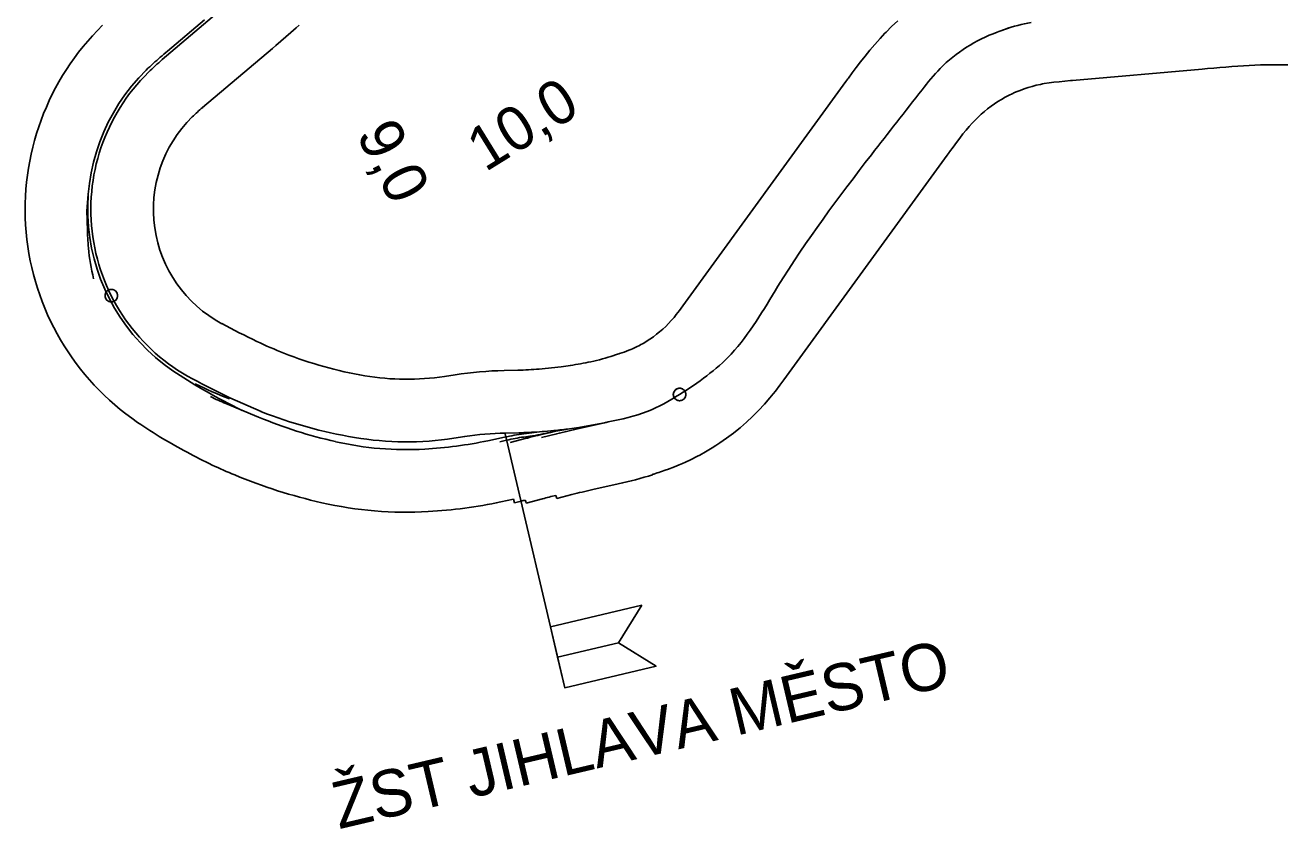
# Model space of a CAD drawing. Extents: x -670810 to -649614, y -1131928 to -1115069.
# Drawn here: x -670304 to -668294, y -1129775 to -1128491 of the extents above; entities that cross this region are included whole.
import ezdxf

# ---------------------------------------------------------------- set-up
doc = ezdxf.new("R2010")
doc.units = 0
for name, color, linetype in [('519 Var SK-4 Praporky stanic', 7, 'Continuous'), ('hranice_VRT_ZUR_Vysocina', 7, 'Continuous'), ('Osa koleje', 7, 'Continuous'), ('Osa koleje úprava GPK', 7, 'Continuous'), ('Situace - Osa koleje 2D', 7, 'Continuous'), ('Staničení - hlavní staničení + kolečka 1k', 7, 'Continuous')]:
    doc.layers.add(name, color=color, linetype=linetype)

# ---------------------------------------------------------------- blocks, each defined once
blk = doc.blocks.new('Sit10Kruh_176')
at = {"layer": 'Staničení - hlavní staničení + kolečka 1k'}
blk.add_lwpolyline([(10, 0), (10, 0.6), (9.9, 1.3), (9.8, 1.9), (9.7, 2.5), (9.5, 3.1), (9.3, 3.7), (9, 4.3), (8.8, 4.8), (8.4, 5.4), (8.1, 5.9), (7.7, 6.4), (7.3, 6.8), (6.8, 7.3), (6.4, 7.7), (5.9, 8.1), (5.4, 8.4), (4.8, 8.8), (4.3, 9), (3.7, 9.3), (3.1, 9.5), (2.5, 9.7), (1.9, 9.8), (1.3, 9.9), (0.6, 10), (0, 10), (-0.6, 10), (-1.3, 9.9), (-1.9, 9.8), (-2.5, 9.7), (-3.1, 9.5), (-3.7, 9.3), (-4.3, 9), (-4.8, 8.8), (-5.4, 8.4), (-5.9, 8.1), (-6.4, 7.7), (-6.8, 7.3), (-7.3, 6.8), (-7.7, 6.4), (-8.1, 5.9), (-8.4, 5.4), (-8.8, 4.8), (-9, 4.3), (-9.3, 3.7), (-9.5, 3.1), (-9.7, 2.5), (-9.8, 1.9), (-9.9, 1.3), (-10, 0.6), (-10, 0), (-10, -0.6), (-9.9, -1.3), (-9.8, -1.9), (-9.7, -2.5), (-9.5, -3.1), (-9.3, -3.7), (-9, -4.3), (-8.8, -4.8), (-8.4, -5.4), (-8.1, -5.9), (-7.7, -6.4), (-7.3, -6.8), (-6.8, -7.3), (-6.4, -7.7), (-5.9, -8.1), (-5.4, -8.4), (-4.8, -8.8), (-4.3, -9), (-3.7, -9.3), (-3.1, -9.5), (-2.5, -9.7), (-1.9, -9.8), (-1.3, -9.9), (-0.6, -10), (0, -10), (0.6, -10), (1.3, -9.9), (1.9, -9.8), (2.5, -9.7), (3.1, -9.5), (3.7, -9.3), (4.3, -9), (4.8, -8.8), (5.4, -8.4), (5.9, -8.1), (6.4, -7.7), (6.8, -7.3), (7.3, -6.8), (7.7, -6.4), (8.1, -5.9), (8.4, -5.4), (8.8, -4.8), (9, -4.3), (9.3, -3.7), (9.5, -3.1), (9.7, -2.5), (9.8, -1.9), (9.9, -1.3)], close=True, dxfattribs=at)
blk.add_circle((0, 0), 10, dxfattribs=at)
blk = doc.blocks.new('Sit10Kruh_230')
at = {"layer": 'Staničení - hlavní staničení + kolečka 1k'}
blk.add_lwpolyline([(10, 0), (10, 0.6), (9.9, 1.3), (9.8, 1.9), (9.7, 2.5), (9.5, 3.1), (9.3, 3.7), (9, 4.3), (8.8, 4.8), (8.4, 5.4), (8.1, 5.9), (7.7, 6.4), (7.3, 6.8), (6.8, 7.3), (6.4, 7.7), (5.9, 8.1), (5.4, 8.4), (4.8, 8.8), (4.3, 9), (3.7, 9.3), (3.1, 9.5), (2.5, 9.7), (1.9, 9.8), (1.3, 9.9), (0.6, 10), (0, 10), (-0.6, 10), (-1.3, 9.9), (-1.9, 9.8), (-2.5, 9.7), (-3.1, 9.5), (-3.7, 9.3), (-4.3, 9), (-4.8, 8.8), (-5.4, 8.4), (-5.9, 8.1), (-6.4, 7.7), (-6.8, 7.3), (-7.3, 6.8), (-7.7, 6.4), (-8.1, 5.9), (-8.4, 5.4), (-8.8, 4.8), (-9, 4.3), (-9.3, 3.7), (-9.5, 3.1), (-9.7, 2.5), (-9.8, 1.9), (-9.9, 1.3), (-10, 0.6), (-10, 0), (-10, -0.6), (-9.9, -1.3), (-9.8, -1.9), (-9.7, -2.5), (-9.5, -3.1), (-9.3, -3.7), (-9, -4.3), (-8.8, -4.8), (-8.4, -5.4), (-8.1, -5.9), (-7.7, -6.4), (-7.3, -6.8), (-6.8, -7.3), (-6.4, -7.7), (-5.9, -8.1), (-5.4, -8.4), (-4.8, -8.8), (-4.3, -9), (-3.7, -9.3), (-3.1, -9.5), (-2.5, -9.7), (-1.9, -9.8), (-1.3, -9.9), (-0.6, -10), (0, -10), (0.6, -10), (1.3, -9.9), (1.9, -9.8), (2.5, -9.7), (3.1, -9.5), (3.7, -9.3), (4.3, -9), (4.8, -8.8), (5.4, -8.4), (5.9, -8.1), (6.4, -7.7), (6.8, -7.3), (7.3, -6.8), (7.7, -6.4), (8.1, -5.9), (8.4, -5.4), (8.8, -4.8), (9, -4.3), (9.3, -3.7), (9.5, -3.1), (9.7, -2.5), (9.8, -1.9), (9.9, -1.3)], close=True, dxfattribs=at)
blk.add_circle((0, 0), 10, dxfattribs=at)
blk = doc.blocks.new('_U648')
at = {"layer": 'Staničení - hlavní staničení + kolečka 1k', "rotation": -63.32941}
blk.add_blockref('Sit10Kruh_230', (-261.6, -148.2), dxfattribs=at)
at = {"layer": 'Staničení - hlavní staničení + kolečka 1k'}
blk.add_text('9,0', height=70, rotation=296.6706, dxfattribs=at).set_placement((129.2, 109.6))

msp = doc.modelspace()

# ---------------------------------------------------------------- linework, layer by layer
at = {"layer": '519 Var SK-4 Praporky stanic'}
for p, q in [((-669537, -1129143.7), (-669441.6, -1129549.6)), ((-669464.5, -1129452.3), (-669318.4, -1129417.9)), ((-669453, -1129500.9), (-669355.7, -1129478))]:
    msp.add_line(p, q, dxfattribs=at)
for points in [[(-669318.4, -1129417.9), (-669355.7, -1129478), (-669453, -1129500.9), (-669464.5, -1129452.3)], [(-669453, -1129500.9), (-669355.7, -1129478), (-669355.7, -1129478), (-669295.5, -1129515.3), (-669441.6, -1129549.6)]]:
    msp.add_lwpolyline(points, close=True, dxfattribs=at)
at = {"layer": 'hranice_VRT_ZUR_Vysocina'}
for p, q in [((-669516.7, -1129042.2), (-669538.5, -1129042.7)), ((-669482.7, -1129040.4), (-669467.7, -1129039)), ((-669447.5, -1129036.7), (-669432.6, -1129034.7)), ((-669633.9, -1129052.1), (-669616.6, -1129049.4)), ((-669396.7, -1129233), (-669356.1, -1129223.9)), ((-669477.3, -1129247.7), (-669503.2, -1129254.5)), ((-669454.4, -1129247), (-669455.6, -1129242.2)), ((-669430.2, -1129240.9), (-669454.4, -1129247)), ((-669543.8, -1129252.8), (-669523.4, -1129248.5)), ((-669522.1, -1129254.1), (-669523.4, -1129248.5)), ((-669522.1, -1129254.1), (-669511.2, -1129251.5)), ((-669503.2, -1129254.5), (-669504.3, -1129250))]:
    msp.add_line(p, q, dxfattribs=at)
for points in [[(-669866.1, -1128490.7), (-669870.9, -1128495.1), (-669879.2, -1128502.5), (-669887.4, -1128509.7), (-669895.5, -1128516.6), (-669903.3, -1128523.3), (-669908.9, -1128528), (-670020.3, -1128622.4)], [(-669363.2, -1129018.8), (-669361.8, -1129018.4), (-669357.2, -1129016.8), (-669355.3, -1129016.2), (-669354.1, -1129015.8), (-669346.7, -1129013.2), (-669339.2, -1129010.3), (-669335.8, -1129009), (-669333.3, -1129007.9), (-669331.2, -1129006.9), (-669327.8, -1129005.4), (-669321.1, -1129002), (-669320.9, -1129001.9), (-669316.3, -1128999.4), (-669310.2, -1128995.7), (-669308.2, -1128994.5), (-669305.5, -1128992.7), (-669299.9, -1128988.8), (-669294.7, -1128984.9), (-669290.1, -1128981.2), (-669284.9, -1128976.7), (-669280.2, -1128972.3), (-669275.7, -1128967.8), (-669271.3, -1128963.1), (-669266.9, -1128958), (-669264.5, -1128955), (-669263.2, -1128953.4), (-669258.2, -1128946.8), (-669252.8, -1128939.5), (-668992.1, -1128581.2), (-668988.8, -1128576.6), (-668988.1, -1128575.6), (-668981.9, -1128567.2), (-668975.5, -1128558.5), (-668968.7, -1128549.5), (-668961.6, -1128540.4), (-668954, -1128531.1), (-668946, -1128521.6), (-668937.6, -1128512.1), (-668929.7, -1128503.8), (-668928, -1128502), (-668919.1, -1128493.2), (-668909.3, -1128484.2)], [(-669301.1, -1129208.9), (-669300, -1129208.6), (-669299.4, -1129208.4), (-669293.8, -1129206.5), (-669291.2, -1129205.6), (-669288.7, -1129204.8), (-669279.3, -1129201.5), (-669277.2, -1129200.7), (-669266, -1129196.5), (-669258.9, -1129193.6), (-669253.4, -1129191.3), (-669248.3, -1129189), (-669240.7, -1129185.4), (-669229.5, -1129179.8), (-669225.8, -1129177.9), (-669216.8, -1129172.9), (-669205.7, -1129166.3), (-669200, -1129162.7), (-669193.6, -1129158.5), (-669182.8, -1129151), (-669172, -1129142.9), (-669163.2, -1129135.8), (-669161.4, -1129134.4), (-669160.5, -1129133.6), (-669151.1, -1129125.4), (-669141.2, -1129116.2), (-669131.6, -1129106.6), (-669122.4, -1129096.6), (-669113.7, -1129086.6), (-669108.4, -1129080.1), (-669104.9, -1129075.6), (-669097.8, -1129066.2), (-669091.3, -1129057.4), (-668830.4, -1128698.8), (-668827.1, -1128694.3), (-668826.6, -1128693.5), (-668820.9, -1128685.8), (-668815.5, -1128678.5), (-668810.2, -1128671.5), (-668805, -1128664.8), (-668800, -1128658.6), (-668795, -1128652.8), (-668790.2, -1128647.3), (-668785.7, -1128642.6), (-668780.7, -1128637.7), (-668775.8, -1128633.1), (-668770.7, -1128628.7), (-668765.6, -1128624.5), (-668760.2, -1128620.5), (-668754.7, -1128616.6), (-668749.2, -1128613), (-668743.5, -1128609.5), (-668737.6, -1128606.1), (-668732.1, -1128603.2), (-668725.2, -1128599.9), (-668723.7, -1128599.2), (-668719.8, -1128597.5), (-668713.7, -1128595.1), (-668707.1, -1128592.7), (-668700.7, -1128590.6), (-668694.3, -1128588.7), (-668687.8, -1128587), (-668680.9, -1128585.5), (-668677.8, -1128584.9), (-668675, -1128584.4), (-668667.4, -1128583.2), (-668659.7, -1128582.2), (-668651.3, -1128581.3), (-668642.4, -1128580.4), (-668633, -1128579.6), (-668629.8, -1128579.3), (-668422.8, -1128561.1), (-668414, -1128560.4), (-668404.2, -1128559.5), (-668394.4, -1128558.7), (-668384.8, -1128557.9), (-668375.3, -1128557.2), (-668365.9, -1128556.5), (-668356.7, -1128555.9), (-668347.5, -1128555.4), (-668338.4, -1128554.9), (-668329.4, -1128554.6), (-668320.5, -1128554.3), (-668311.7, -1128554.1), (-668304.3, -1128554.1), (-668303.3, -1128554.1), (-668294.9, -1128554.2), (-668294.8, -1128554.2), (-668286, -1128554.4)]]:
    msp.add_lwpolyline(points, dxfattribs=at)
for centre, radius, start, end in [((-669892, -1128785.4), 412, 134.4338, 235.6917), ((-669820.3, -1128858.4), 309.4, 130.2667, 134.4669), ((-669892, -1128785.4), 207, 134.4669, 241.8609), ((-669328.2, -1127731.2), 1402.4, 241.8609, 244.4303), ((-669648.7, -1128400.9), 660, 244.4303, 248.5158), ((-669653, -1128411.9), 648.3, 248.5158, 260.4135), ((-669485.9, -1128638), 400.1, 282.4063, 287.8575), ((-669526.1, -1129642.6), 600, 91.1888, 98.6813), ((-669527.1, -1128541.9), 500.5, 271.1888, 275.097), ((-669505, -1128621.1), 419.6, 275.097, 277.8775), ((-669487.5, -1128638.4), 400, 277.8775, 282.6411), ((-669694.3, -1128656.7), 400, 260.4135, 278.6813), ((-669639.5, -1128415.3), 860, 235.6917, 238.8267), ((-669507.6, -1128168.9), 1139.2, 239.5661, 244.1166), ((-669639.5, -1128415.3), 860, 244.8559, 247.4628), ((-669639.5, -1128415.3), 860, 247.4628, 257.2041), ((-669483.9, -1128637.5), 600.2, 282.2858, 287.7369), ((-669223.2, -1130212.6), 997.8, 103.4682, 104.7534), ((-669090.4, -1130599.1), 1400, 102.6411, 104.0476), ((-669694.3, -1128656.7), 612.5, 257.2041, 273.2303), ((-669703.5, -1128493.6), 775.8, 273.2303, 281.8799), ((-669464.8, -1129446), 200, 101.4059, 103.4219)]:
    msp.add_arc(centre, radius, start, end, dxfattribs=at)
at = {"layer": 'Osa koleje'}
for p, q in [((-670203.1, -1128760.9), (-670205.2, -1128787.9)), ((-670202.1, -1128761), (-670204.1, -1128760.8)), ((-670205.2, -1128787.9), (-670204.5, -1128815)), ((-670205.2, -1128787.9), (-670202.6, -1128814.9)), ((-670203.5, -1128815), (-670205.5, -1128815.1)), ((-670201.6, -1128814.8), (-670203.6, -1128815)), ((-670201.8, -1128847), (-670203.8, -1128847.2)), ((-669490.3, -1129141.4), (-669506.9, -1129142)), ((-669490.3, -1129141.4), (-669506.8, -1129143.8)), ((-669480.6, -1129145.3), (-669497.1, -1129147.6)), ((-669480.6, -1129145.3), (-669496.7, -1129149.4)), ((-669473.8, -1129140), (-669490.3, -1129141.4)), ((-669464.4, -1129141.6), (-669480.6, -1129145.3)), ((-669446.3, -1129137.5), (-669458.8, -1129138.6)), ((-669446.3, -1129137.5), (-669458.6, -1129140.3)), ((-669433.8, -1129135.8), (-669446.3, -1129137.5))]:
    msp.add_line(p, q, dxfattribs=at)
for centre, radius, start, end in [((-669527.1, -1128541.9), 600.5, 271.927, 275.0971), ((-669420.4, -1129738.1), 600.5, 95.0971, 98.2672), ((-669555.2, -1128738.5), 413.2, 278.0859, 282.6918), ((-669223.2, -1130212.6), 1097.8, 102.6918, 104.4261), ((-669505, -1128621.1), 519.6, 275.0971, 277.8776), ((-669392.7, -1129433), 300, 97.8776, 102.6917)]:
    msp.add_arc(centre, radius, start, end, dxfattribs=at)
at = {"layer": 'Osa koleje úprava GPK'}
msp.add_arc((-668641, -1128783.5), 302, 108.8552, 111.2858, dxfattribs=at)
at = {"layer": 'Situace - Osa koleje 2D'}
for p, q in [((-669973.6, -1128451.7), (-670084.9, -1128546)), ((-670017.5, -1128482.4), (-670076.5, -1128532.4)), ((-670067.9, -1129043.1), (-670032.9, -1129065.6)), ((-669976.7, -1129086.5), (-669927, -1129108.1)), ((-669983.2, -1129095.5), (-669930.8, -1129117.3)), ((-669980.1, -1129094.7), (-669957, -1129106.4)), ((-669418.9, -1129133.7), (-669375.1, -1129125.7)), ((-669418.6, -1129135.4), (-669378, -1129126.3)), ((-669514.7, -1129142.2), (-669536.4, -1129142.7)), ((-669454.4, -1129143.9), (-669478.7, -1129150)), ((-669473.8, -1129140), (-669458.8, -1129138.6)), ((-669464.4, -1129141.6), (-669458.6, -1129140.3)), ((-669433.8, -1129135.8), (-669418.9, -1129133.7)), ((-669618.9, -1129150.9), (-669601.5, -1129148.3)), ((-669564.4, -1129154.9), (-669537.8, -1129149.3)), ((-669545.3, -1129156.8), (-669534.4, -1129154.2)), ((-669502.8, -1129151), (-669528.6, -1129157.8)), ((-669507, -1129149), (-669497.1, -1129147.6))]:
    msp.add_line(p, q, dxfattribs=at)
msp.add_lwpolyline([(-670076.5, -1128532.4), (-670079.4, -1128534.9), (-670082.3, -1128537.3), (-670085.2, -1128539.8), (-670088.1, -1128542.2), (-670090.9, -1128544.7), (-670093.8, -1128547.2), (-670096.6, -1128549.7), (-670099.4, -1128552.2), (-670102.2, -1128554.8), (-670105, -1128557.3), (-670107.7, -1128559.9), (-670110.4, -1128562.6)], dxfattribs=at)
for centre, radius, start, end in [((-668641, -1128783.5), 302, 100.5125, 108.8552), ((-669892, -1128785.4), 312, 134.4338, 235.6917), ((-669820.3, -1128858.4), 409.4, 130.2667, 134.4669), ((-669892, -1128785.4), 307, 134.4669, 241.8609), ((-669673.8, -1128802.5), 530.9, 175.5063, 181.3521), ((-669892, -1128785.4), 312, 175.5063, 185.4377), ((-669673.8, -1128802.5), 530.9, 181.3521, 184.8211), ((-669903.9, -1128821.9), 300, 184.8211, 194.3174), ((-669328.2, -1127731.2), 1502.4, 241.8609, 244.4303), ((-669639.5, -1128415.3), 760, 238.8267, 243.3772), ((-669721.1, -1128436.9), 700, 243.6251, 248.5158), ((-669791.5, -1128633.7), 500, 244.3751, 247.4628), ((-669639.5, -1128415.3), 760, 247.4628, 257.2041), ((-669653, -1128411.9), 748.3, 248.5158, 260.4135), ((-669487.5, -1128638.4), 500, 282.6411, 283.3287), ((-669526.1, -1129642.6), 500, 91.1888, 98.6813), ((-669434.9, -1129638.6), 500, 98.267, 101.8799), ((-669527.1, -1128541.9), 600.5, 271.1888, 271.927), ((-669090.4, -1130599.1), 1500, 102.6411, 104.0476), ((-669694.3, -1128656.7), 512.5, 257.2041, 273.2303), ((-669694.3, -1128656.7), 500, 260.4135, 278.6813), ((-669703.5, -1128493.6), 675.8, 273.2303, 281.8799), ((-669464.8, -1129446), 300, 98.086, 103.4219), ((-669223.2, -1130212.6), 1097.8, 104.426, 104.7534)]:
    msp.add_arc(centre, radius, start, end, dxfattribs=at)
msp.add_spline([(-669372.2, -1129125), (-669309.6, -1129108.2), (-669258, -1129081), (-669175.7, -1129016.5), (-669100.8, -1128908.2), (-668951.4, -1128697.9), (-668870.3, -1128594.2), (-668841.5, -1128560.2), (-668750.6, -1128502.1), (-668726.4, -1128493.8)], degree=3, dxfattribs=at)

# ---------------------------------------------------------------- block references
at = {"layer": 'Staničení - hlavní staničení + kolečka 1k'}
msp.add_blockref('_U648', (-669904.7, -1128774.9), dxfattribs=at)
at = {"layer": 'Staničení - hlavní staničení + kolečka 1k', "rotation": 31.750231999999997}
msp.add_blockref('Sit10Kruh_176', (-669258, -1129081), dxfattribs=at)

# ---------------------------------------------------------------- texts
at = {"layer": '519 Var SK-4 Praporky stanic'}
msp.add_text('ŽST JIHLAVA MĚSTO', height=75, rotation=13.2363, dxfattribs=at).set_placement((-669802.6, -1129775.8))
at = {"layer": 'Staničení - hlavní staničení + kolečka 1k'}
msp.add_text('10,0', height=70, rotation=31.7502, dxfattribs=at).set_placement((-669568.7, -1128726.5))

doc.saveas('drawing.dxf')
